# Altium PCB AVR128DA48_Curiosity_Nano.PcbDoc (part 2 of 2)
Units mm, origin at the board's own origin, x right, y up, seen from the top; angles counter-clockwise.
Board outline 83.82 x 20.32 mm, 4 copper layers (Top-Layer, Ground Plane, Power Plane, Bottom Layer), stack 1.59 mm thick; 66 components, 98 nets, 469 pads, 191 vias.
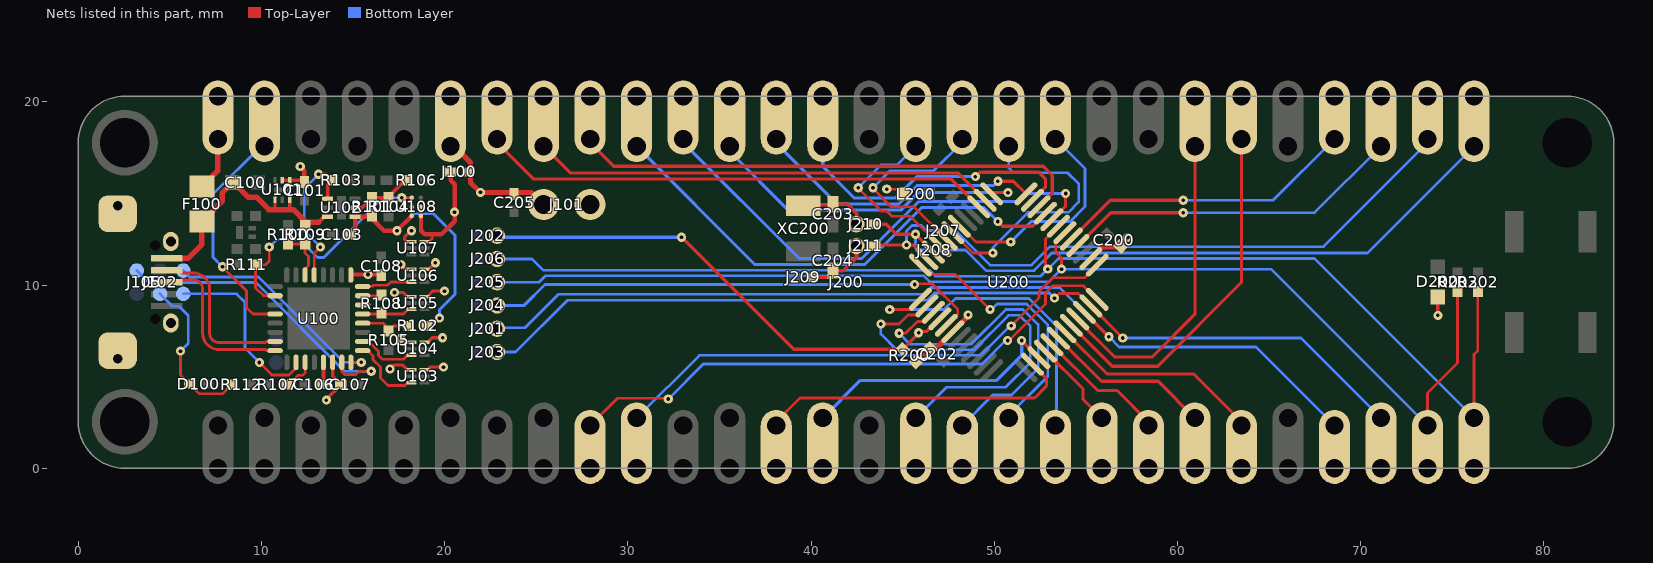
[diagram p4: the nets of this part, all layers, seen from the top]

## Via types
v1: diameter 0.5, hole 0.2, Top-Layer to Bottom Layer, 187 vias
v2: diameter 0.5, hole 0.2, Top-Layer to Bottom Layer, tented both sides, 2 vias
v3: diameter 0.5, hole 0.2, Top-Layer to Bottom Layer, tented top, 2 vias

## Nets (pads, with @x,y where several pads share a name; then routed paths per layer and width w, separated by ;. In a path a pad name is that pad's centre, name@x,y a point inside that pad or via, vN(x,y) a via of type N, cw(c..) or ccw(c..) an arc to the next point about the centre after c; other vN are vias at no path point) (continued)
PA6_SPI0_SCK: J200.13 U200.2 | length 17.1
  Top-Layer w0.175: J200.13@38.1,2.54 39.398,3.838 52.203,3.838 52.852,4.486 52.852,4.926 U200.2@52.09,5.688
PA7_SPI0_SS: J200.14 U200.3 | length 14.4
  Top-Layer w0.175: v1(51.5,6.975) 51.51,6.975 U200.3@52.444,6.041
  Bottom Layer w0.175: J200.14@40.64,2.743 42.697,4.8 50.13,4.8 51.5,6.17 v1(51.5,6.975)
PB0_UART3_TX: J200.20 U200.4 | length 4.9
  Top-Layer w0.175: U200.4@52.798,6.395 54.85,4.342 54.85,3.773 J200.20@55.88,2.743
PB1_UART3_RX: J200.21 U200.5 | length 7
  Top-Layer w0.175: U200.5@53.151,6.748 55.649,4.25 56.71,4.25 J200.21@58.42,2.54
PB2: J200.22 U200.6 | length 9.5
  Top-Layer w0.175: U200.6@53.505,7.102 55.856,4.75 58.953,4.75 J200.22@60.96,2.743 J200.22@60.96,2.54
PB3: J200.23 U200.7 | length 11.7
  Top-Layer w0.175: U200.7@53.858,7.455 56.164,5.15 60.89,5.15 J200.23@63.5,2.54
PB4: J200.34 U200.8 | length 19.7
  Top-Layer w0.175: U200.8@54.212,7.809 56.446,5.575 58.925,5.575 63.5,10.15 J200.34@63.5,17.78
PB5: J200.35 U200.9 | length 17.6
  Top-Layer w0.175: U200.9@54.565,8.162 54.565,8.083 56.573,6.075 58.625,6.075 60.96,8.41 J200.35@60.96,17.577 J200.35@60.96,17.78
PC0_UART1_TX: J200.25 J201.2 U200.10 | length 51.7
  Top-Layer w0.175: U200.10@54.919,8.516 56.261,7.174 v1@56.261,7.112
  Bottom Layer w0.15: J201.2@22.86,7.62 22.915,7.675 24.382,7.675 26.211,9.504 46.162,9.504 46.534,9.875 53.573,9.875 v1(56.261,7.187) 56.819,6.629 64.287,6.629 J200.25@68.58,2.337
PC1_UART1_RX: J200.26 J203.2 U200.11 | length 52.7
  Top-Layer w0.15: v1(53.291,9.292) 53.541,9.541 54.601,9.541 U200.11@55.272,8.87
  Top-Layer w0.175: U200.11@55.272,8.87 56.896,7.246 56.896,7.112 v1(57.023,7.112)
  Bottom Layer w0.15: J203.2@22.86,6.35 23.869,6.35 26.694,9.175 46.351,9.175 46.752,9.575 53.007,9.575 v1(53.291,9.292) ; v1(57.023,7.112) 66.751,7.112 J200.26@71.12,2.743
PC2_I2C0_SDA: J200.9 U200.12 | length 31.5
  Top-Layer w0.15: J200.9@27.94,2.337 29.422,3.819 32.175,3.819 v1(32.209,3.785) ; v1(50.736,6.975) 50.799,6.975 52.798,8.974 52.798,9.573 53.189,9.964 54.882,9.964 55.624,9.223 U200.12@55.626,9.223
  Bottom Layer w0.15: v1(32.209,3.785) 34.118,5.694 49.345,5.694 50.625,6.975 v1(50.736,6.975)
PC3_I2C0_SCL: J200.10 U200.13 | length 28.8
  Top-Layer w0.15: v1(50.927,7.775) 52.444,9.292 52.444,9.643 53.199,10.398 54.927,10.398 U200.13@55.626,11.097
  Bottom Layer w0.15: J200.10@30.48,2.743 33.906,6.17 49.259,6.17 50.864,7.775 v1(50.927,7.775)
PC4: J200.31 U200.16 | length 18.8
  Top-Layer w0.175: U200.16@54.565,12.158 56.363,13.955 v1(60.325,13.955)
  Bottom Layer w0.15: v1(60.325,13.955) 67.498,13.955 J200.31@71.12,17.577
PC5: J200.32 U200.17 | length 16.6
  Top-Layer w0.175: U200.17@54.212,12.511 56.333,14.632 v1(60.325,14.632)
  Bottom Layer w0.15: v1(60.325,14.632) 65.229,14.632 J200.32@68.58,17.983
PC6_LED0_GPIO1: J200.27 J205.2 R203.1 U200.18 | length 65.2
  Top-Layer w0.15: v1(53.671,10.873) 53.671,11.487 53.359,11.799 53.359,12.366 U200.18@53.858,12.865 ; J200.27@73.66,2.337 73.66,4.115 75.3,5.755 R203.1@75.3,9.656
  Bottom Layer w0.15: J205.2@22.86,10.16 25.16,10.16 25.516,10.516 46.134,10.516 46.461,10.189 52.987,10.189 v1(53.671,10.873) 65.123,10.873 J200.27@73.66,2.337
PC7_SW0_GPIO0: J200.28 J206.2 R202.1 U200.19 | length 72.3
  Top-Layer w0.15: v1(52.928,10.873) 52.802,10.999 52.802,12.516 U200.19@53.505,13.218 ; J200.28@76.2,0.325 J200.28@76.2,2.743 76.2,6.223 76.405,6.428 R202.1@76.405,9.656
  Bottom Layer w0.15: J206.2@22.86,11.43 24.763,11.43 25.377,10.816 46.467,10.816 46.794,10.489 52.543,10.489 v1(52.928,10.873) 53.515,11.461 67.483,11.461 J200.28@76.2,2.743 J200.28@76.2,0.325
PD0_AIN0_WO0: J200.46 U200.20 | length 26.7
  Top-Layer w0.175: U200.20@53.151,13.572 53.9,14.321 v1(53.9,15)
  Bottom Layer w0.175: J200.46@33.02,17.78 39.347,11.453 42.76,11.453 45.869,14.563 51.299,14.563 51.737,15 v1(53.9,15)
PD1_AIN1_WO1: J200.47 U200.21 | length 27.2
  Top-Layer w0.175: v1(50.202,13.476) 50.46,13.218 52.09,13.218 U200.21@52.798,13.925
  Bottom Layer w0.175: J200.47@30.48,17.78 J200.47@30.48,17.577 36.929,11.128 42.939,11.128 46.049,14.238 49.441,14.238 v1(50.202,13.476)
PD2_AIN2_WO2: J200.48 U200.22 | length 28
  Top-Layer w0.175: J200.48@27.94,17.78 29.232,16.488 52.673,16.488 53.175,15.987 53.175,15.01 U200.22@52.444,14.279
PD3_AIN3: J200.43 U200.23 | length 16.4
  Top-Layer w0.175: v1(48.975,15.925) 49.213,16.163 52.436,16.163 52.798,15.802 52.798,15.34 U200.23@52.09,14.632
  Bottom Layer w0.175: J200.43@40.64,17.78 J200.43@40.64,17.577 40.64,16.485 42.375,14.75 44.607,14.75 45.782,15.925 v1(48.975,15.925)
PD4_AIN4: J200.44 U200.24 | length 15.8
  Top-Layer w0.175: v1(50.2,15.675) 51.048,15.675 U200.24@51.737,14.986
  Bottom Layer w0.175: J200.44@38.1,17.748 41.423,14.425 44.775,14.425 45.787,15.438 49.963,15.438 v1(50.2,15.675)
PD5_AIN5: J200.45 U200.25 | length 18.1
  Top-Layer w0.175: U200.25@49.863,14.986 49.927,15.05 v1(50.75,15.05)
  Bottom Layer w0.175: J200.45@35.56,17.545 35.56,17.295 38.755,14.1 44.909,14.1 45.859,15.05 v1(50.75,15.05)
PD6_AIN6: J200.49 U200.26 | length 25.5
  Top-Layer w0.175: J200.49@25.4,17.78 J200.49@25.4,17.577 26.85,16.127 48.015,16.127 U200.26@49.51,14.632
PD7_AIN7: J200.50 U200.27 | length 27.7
  Top-Layer w0.175: J200.50@22.86,17.78 24.838,15.802 47.633,15.802 U200.27@49.156,14.279
PE0: J200.38 U200.30 | length 12.4
  Top-Layer w0.15: U200.30@48.095,13.218 48.136,13.218 49.004,12.351 50.896,12.351 v1(50.906,12.36)
  Bottom Layer w0.15: v1(50.906,12.36) 52.025,13.479 54.15,13.479 54.962,14.291 54.962,16.361 J200.38@53.34,17.983
PE1: J200.39 U200.31 | length 15
  Top-Layer w0.15: U200.31@47.742,12.865 48.845,11.761 v1(49.93,11.761)
  Bottom Layer w0.15: v1(49.93,11.761) 49.93,12.056 51.849,13.975 54.05,13.975 54.61,14.535 54.61,15.54 54.017,16.133 51.06,16.133 50.8,16.392 J200.39@50.8,17.577
PE2: J200.40 U200.32 | length 11.3
  Top-Layer w0.15: v1(43.386,15.315) 43.386,15.269 44.381,14.274 45.625,14.274 U200.32@47.388,12.511
  Bottom Layer w0.15: v1(43.386,15.315) 44.317,16.245 46.693,16.245 48.26,17.812 J200.40@48.26,17.983
PE3: J200.41 U200.33 | length 9.8
  Top-Layer w0.15: v1(42.576,15.315) 43.855,14.035 44.157,14.035 44.436,13.755 45.437,13.755 U200.33@47.035,12.158
  Bottom Layer w0.15: v1(42.576,15.315) 43.822,16.56 44.704,16.56 J200.41@45.72,17.577
PF0: J200.29 J208.2 | length 32.4
  Bottom Layer w0.15: J208.2@47.094,11.913 48.437,11.913 49.561,10.789 52.172,10.789 53.143,11.761 56.689,11.761 70.384,11.761 J200.29@76.2,17.577
PF0_TOSC1: J208.1 J210.1 U200.34 | length 5.2
  Top-Layer w0.175: J210.1@43.546,13.326 44.111,13.326 44.657,12.78 v1(45.705,12.78) U200.34@46.681,11.804
  Bottom Layer w0.15: v1(45.705,12.78) 45.705,12.073 45.86,11.918 J208.1@46.344,11.918
PF1: J200.30 J207.2 | length 29.6
  Bottom Layer w0.15: J207.2@47.594,12.979 47.889,12.979 49.779,11.089 52.047,11.089 53.058,12.1 56.792,12.1 67.98,12.1 J200.30@73.66,17.78
PF1_TOSC2: J207.1 J211.1 U200.35 | length 5.7
  Top-Layer w0.175: J211.1@43.597,12.192 v1(45.212,12.192) 45.586,12.192 U200.35@46.328,11.45
  Bottom Layer w0.15: v1(45.212,12.192) 45.212,12.959 45.508,13.255 46.022,13.255 46.298,12.979 J207.1@46.844,12.979
PF2: J200.18 U200.36 | length 14.5
  Top-Layer w0.15: U200.36@45.974,11.097 46.473,10.598 47.854,10.598 v1(49.777,8.675)
  Bottom Layer w0.15: v1(49.777,8.675) 49.849,8.675 50.149,8.975 51.775,8.975 52.928,7.822 52.928,5.028 50.8,2.9 J200.18@50.8,2.743
PF3: J200.19 U200.37 | length 17.3
  Top-Layer w0.15: v1(44.299,8.665) 45.416,8.665 U200.37@45.974,9.223
  Bottom Layer w0.15: v1(44.299,8.665) 47.271,8.665 47.882,9.275 51.899,9.275 53.4,7.774 53.4,2.397 J200.19@53.34,2.337
PF4_UART2_TX: J200.16 U200.38 | length 22.5
  Top-Layer w0.15: v1(43.812,7.88) 44.804,7.88 45.289,8.365 45.823,8.365 U200.38@46.328,8.87
  Bottom Layer w0.15: v1(43.812,7.88) 43.812,7.324 44.661,6.475 48.902,6.475 50.777,8.35 51.387,8.35 51.975,7.762 51.975,5.775 50.624,4.424 47.401,4.424 J200.16@45.72,2.743
PF5_UART2_RX: J200.17 U200.39 | length 19.1
  Top-Layer w0.15: v1(44.812,7.377) 45.173,7.377 45.813,8.017 46.182,8.017 U200.39@46.681,8.516
  Bottom Layer w0.15: v1(44.812,7.377) 45.414,6.775 48.737,6.775 50.637,8.675 51.575,8.675 52.4,7.85 52.4,5.453 50.947,4 49.923,4 J200.17@48.26,2.337
PF6_RESET: J202.2 R200.2 U200.40 | length 27.4
  Top-Layer w0.175: v1(32.933,12.618) 39.047,6.504 R200.2@45.006,6.504 45.006,6.506 45.877,7.377 v1(45.877,7.4) 45.939,7.463 46.301,7.463 47.001,8.162 U200.40@47.035,8.162
  Bottom Layer w0.175: J202.2@22.95,12.71 23.042,12.618 v1(32.933,12.618)
REG_ADJUST: R101.2 R104.2 R106.1 U102.5 | length 3.4
  Top-Layer w0.2: U102.5@15.115,14.225 15.49,14.225 R101.2@16.04,14.775 16.965,14.775 16.965,14.85 R106.1@17.84,15.725
REG_ENABLE: R103.1 U100.13 U102.1 | length 8.3
  Top-Layer w0.15: U100.13@12.876,10.556 12.876,11.736 v1(13.215,12.075)
  Top-Layer w0.2: v1(13.115,16.05) 13.508,16.05 13.833,15.725 R103.1@13.865,15.725 13.615,15.475 U102.1@13.615,14.725
  Bottom Layer w0.15: v1(13.115,16.05) 12.34,15.275 12.34,12.95 v1(13.215,12.075)
RESERVED: U100.6
S0_0_RX: R108.1 U100.5 U105.3 | length 2.8
  Top-Layer w0.15: U100.5@15.52,8.424 17.74,8.424 17.991,8.675 U105.3@18.189,8.675
S0_2_TX: R108.2 U100.7 | length 1
  Top-Layer w0.15: U100.7@15.52,9.424 R108.2@16.515,9.424
S0_3_CLK: U100.8 U106.3 | length 2.8
  Top-Layer w0.15: U100.8@15.52,9.937 16.055,9.937 16.119,10 16.89,10 17.065,10.175 U106.3@18.189,10.175
S1_0_TX: U100.1 U103.3 | length 4
  Top-Layer w0.15: U100.1@15.52,6.424 15.797,6.424 16.09,6.131 16.09,5.925 16.49,5.525 16.49,4.934 16.905,4.519 17.834,4.519 17.99,4.675 U103.3@18.189,4.675
S1_1_RX: U100.2 U104.3 | length 3.3
  Top-Layer w0.15: U100.2@15.52,6.924 15.841,6.924 16.39,6.375 16.39,6.156 16.596,5.95 17.74,5.95 17.965,6.175 U104.3@18.189,6.175
S\R\S\T\: J102.6 U100.26 | length 9.9
  Top-Layer w0.15: v3(9.885,5.777) 10.562,5.1 11.498,5.1 11.884,5.486 U100.26@11.884,5.787
  Bottom Layer w0.15: J102.6@5.73,9.525 8.64,9.525 9.1,9.065 9.1,6.562 v3(9.885,5.777)
SHIELD: J105.6 J105.7 J105.8 J105.9
STATUS_LED: R107.2 U100.27 | length 1.8
  Top-Layer w0.15: R107.2@11.39,4.575 11.493,4.575 11.993,5.075 12.24,5.075 12.393,5.228 U100.27@12.393,5.777
SWCLK: J102.1 U100.31 | length 17.3
  Top-Layer w0.15: U100.31@14.384,5.787 14.384,5.281 14.544,5.122 15.165,5.122 15.34,5.297 v1(15.99,5.297)
  Bottom Layer w0.15: J102.1@3.19,10.795 3.835,10.15 9.69,10.15 14.543,5.297 v1(15.99,5.297)
SWDIO: J102.5 U100.32 | length 12.4
  Top-Layer w0.15: U100.32@14.88,5.784 v1(15.449,5.784)
  Bottom Layer w0.15: J102.5@5.73,10.795 6.075,10.45 9.84,10.45 14.506,5.784 v1(15.449,5.784)
UPDI: J204.2 U200.41 | length 27.3
  Top-Layer w0.15: v1(45.658,10.035) 45.698,10.075 46.607,10.075 48.017,8.665 48.017,8.438 U200.41@47.388,7.809
  Bottom Layer w0.15: J204.2@22.95,8.885 24.327,8.885 ; 25.477,10.035 v1(45.658,10.035)
  Bottom Layer w0.175: 24.327,8.885 25.477,10.035
USBD_N: J105.2 U100.23 | length 9.2
  Top-Layer w0.16: J105.2@4.83,10.81 5.505,10.81 5.649,10.666 6.281,10.666 cw(c6.281,9.777) 7.17,9.777 7.17,7.375 ccw(c7.681,7.375) 7.681,6.864 10.214,6.864 10.274,6.924 U100.23@10.74,6.924
USBD_P: J105.3 U100.24 | length 9.2
  Top-Layer w0.16: J105.3@4.83,10.16 5.505,10.16 5.631,10.286 6.279,10.286 cw(c6.279,9.775) 6.79,9.775 6.79,7.373 ccw(c7.679,7.373) 7.679,6.484 10.214,6.484 10.274,6.424 U100.24@10.74,6.424
V\O\F\F\: J200.55 U100.20 | length 12.5
  Top-Layer w0.15: v1(7.87,11) 9.175,9.695 9.175,8.79 9.541,8.424 U100.20@10.74,8.424
  Bottom Layer w0.15: v1(7.87,11) 7.346,11.524 7.346,14.966 9.957,17.577 J200.55@10.16,17.577
VBUS: F100.1 J200.56 | length 2.8
  Top-Layer w0.3: F100.1@6.75,15.377 7.62,16.247 J200.56@7.62,17.78
VBUS_ADC: R100.1 R109.1 U100.14 | length 2.8
  Top-Layer w0.15: R100.1@11.439,12.25 12.376,12.25 12.376,11.764 12.565,11.575 12.565,11.068 12.376,10.879 U100.14@12.376,10.556
VCC_EDGE: C205.1 J100.2 J101.1 J200.51 | length 7.1
  Top-Layer w0.25: J200.51@20.32,17.78 J200.51@20.425,17.675
  Top-Layer w0.27: J200.51@20.425,17.675 21.407,16.693 21.407,15.593 21.935,15.065 v1(21.96,15.065) 24.737,15.065 J101.1@25.4,14.402
VCC_LEVEL: J100.1 U103.6 U104.6 U105.6 U106.6 U107.6 U108.A1 U108.B1 | length 11.2
  Top-Layer w0.15: U105.6@18.889,9.375 19.064,9.375 19.089,9.4 19.089,9.414 19.35,9.675 v1(19.99,9.675) ; U107.6@18.889,12.375 18.914,12.4 19.167,12.4 19.315,12.548 19.315,12.767
  Top-Layer w0.175: U103.6@18.889,5.375 19.065,5.375 19.215,5.525 v1(19.94,5.525) ; U104.6@18.889,6.875 19.065,6.875 19.315,7.125 v1(19.89,7.125) ; U106.6@18.889,10.875 19.14,10.875 v1(19.49,11.225)
  Top-Layer w0.2: U108.A1@18.702,13.775 U108.B1@18.702,14.275
  Top-Layer w0.225: 18.702,12.963 U108.A1@18.702,13.775
  Top-Layer w0.25: 18.714,12.963 18.909,12.767 19.315,12.767 19.822,12.767 20.54,13.485 v1(20.54,13.985) 20.54,15.5 20.32,15.72 J100.1@20.32,16.2
VCC_MCU_CORE: C106.2 U100.29 | length 1.2
  Top-Layer w0.2: C106.2@13.34,4.575 13.384,4.619 U100.29@13.384,5.787
VCC_P3V3: C101.2 C107.1 C108.1 D100.2 J102.4 R112.1 U100.9 U100.30 U101.1 U101.2 U103.1 U104.1 U105.1 U106.1 U107.1 | length 20.4
  Top-Layer w0.15: v1(5.575,6.4) 5.575,5.096 D100.2@6.071,4.6 6.596,4.075 7.89,4.075 R112.1@8.39,4.575 ; D100.2@5.99,4.575 D100.2@6.14,4.425
  Top-Layer w0.175: U101.2@11.139,15.725 12.239,15.725 C101.2@12.339,15.625 ; v1(17.015,5.425) 17.228,5.638 17.706,5.638 17.968,5.375 U103.1@18.189,5.375 ; v1(17.264,9.6) 17.74,9.6 17.965,9.375 U105.1@18.189,9.375 ; v1(17.599,11.125) 17.849,10.875 U106.1@18.189,10.875 ; v1(17.615,7.1) 17.84,6.875 U104.1@18.189,6.875 ; U107.1@18.189,12.375 18.177,12.388 17.913,12.388 17.81,12.49 17.81,12.635 18.148,12.973 v1(18.189,12.973)
  Top-Layer w0.2: v1(13.54,3.725) 13.54,3.775 C107.1@14.34,4.575 13.884,5.031 U100.30@13.884,5.787 ; U100.9@14.876,10.581 v1(15.815,10.581) 16.429,10.581 C108.1@16.515,10.495
  Top-Layer w0.25: v1(12.115,16.475) 12.339,16.251 C101.2@12.339,15.625
  Bottom Layer w0.15: J102.4@4.46,9.525 5.135,8.85 5.5,8.85 6,8.35 6,6.825 v1(5.575,6.4)
VCC_REGULATOR: C103.2 R101.1 R102.2 U102.4 U108.A2 U108.B2 | length 15.2
  Top-Layer w0.175: R102.2@19.039,7.875 19.113,7.95 19.465,7.95 v1(19.715,8.2) ; v1@19.765,8.175 v1@19.79,8.2
  Top-Layer w0.2: R101.1@16.04,13.62 R101.1@16.04,13.775 ; U108.A2@18.202,13.775 U108.B2@18.202,14.275
  Top-Layer w0.225: v1(17.4,12.973) U108.A2@18.202,13.775
  Top-Layer w0.24: C103.2@14.845,12.75 15.115,13.02 U102.4@15.115,13.725 15.99,13.725 R101.1@16.04,13.775
  Top-Layer w0.25: R101.1@16.04,13.62 16.687,12.973 v1(17.4,12.973)
  Bottom Layer w0.15: v1(17.4,12.973) 18.327,13.9 19.387,13.9 20.565,12.722 20.565,9.504 19.715,8.654 v1(19.715,8.2)
VCC_TARGET: C200.2 C202.1 D200.2 J101.2 L200.1 R200.1 U200.14 U200.42 | length 8.5
  Top-Layer w0.15: v1(44.131,15.24) 44.938,15.24 L200.1@45.113,15.065
  Top-Layer w0.175: U200.42@47.742,7.455 U200.42@47.742,7.483
  Top-Layer w0.2: v1@74.221,8.504 D200.2@74.221,9.356
  Top-Layer w0.25: v1@74.221,8.504 v1@74.298,8.427
  Top-Layer w0.27: R200.1@45.714,5.796 46.476,6.559 C202.1@46.527,6.559 ; C202.1@46.492,6.594 46.881,6.594 U200.42@47.742,7.455 ; U200.42@47.742,7.483 48.577,8.318 v1(48.577,8.375) ; U200.14@55.245,11.43 55.89,12.075 56.759,12.075 56.759,12.077 v1(57.282,12.6)
  other v1: 74.221,8.35
VCC_VBUS: C100.2 F100.2 J105.1 R109.2 U101.4 U101.6 U102.3 | length 13.8
  Top-Layer w0.175: 10.739,14.151 U101.4@10.739,14.675 ; 11.539,14.151 U101.6@11.539,14.675
  Top-Layer w0.24: 13.115,13.425 13.415,13.725 U102.3@13.615,13.725
  Top-Layer w0.3: J105.1@4.83,11.46 5.989,11.46 6.75,12.221 F100.2@6.75,13.477 7.87,14.597 7.87,15.048 C100.2@8.419,15.597 ; C100.2@8.444,15.622 9.267,14.8 9.724,14.8 10.399,14.125 11.74,14.125 12.389,13.476 R109.2@12.389,13.425 ; R109.2@12.389,13.25 R109.2@12.389,13.425 ; 13.115,13.425 R109.2@12.389,13.425
VTG_ADC: R102.1 R105.2 U100.4 | length 2.8
  Top-Layer w0.15: U100.4@15.52,7.924 16.64,7.924 R105.2@17.003,7.561 ; R105.2@16.94,7.499 R105.2@17.003,7.561 ; R102.1@18.039,7.775 17.216,7.775 R105.2@17.003,7.561
VTG_EN: R111.1 U100.18 U108.C2 | length 13.8
  Top-Layer w0.15: v1(10.425,12.075) 10.425,11.321 10.216,11.112 R111.1@9.675,11.112 9.675,9.85 10.101,9.424 U100.18@10.74,9.424 ; v1(17.659,14.775) U108.C2@18.202,14.775
  Bottom Layer w0.15: v1(10.425,12.075) 10.825,12.475 12.09,12.475 13.058,11.507 13.397,11.507 16.665,14.775 v1(17.659,14.775)
XIN: C203.2 J210.2 XC200.2 | length 3.7
  Top-Layer w0.2: XC200.2@39.572,14.381 C203.2@41.153,14.381 ; C203.2@41.196,14.424 41.976,14.424 42.5,13.9 J210.2@42.5,13.326
XOUT: C204.1 J209.1 J211.2 | length 3.1
  Top-Layer w0.18: J209.1@40.047,10.428 C204.1@40.937,10.428
  Top-Layer w0.2: C204.1@41.196,10.788 41.763,10.788 42.48,11.505 J211.2@42.48,12.088
pads on no net: J102.3 J105.0 J105.4 J105.10 J105.11 J200.0 J207.5 J208.5 Q101.0 U101.0 U101.5 U103.0 U104.0 U105.0 U106.0 U107.0

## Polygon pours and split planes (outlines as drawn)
GND on Bottom Layer "Bottom Layer-GND" (solid, remove dead copper, pour order 2): 83.82,20.32 83.82,0 0,0 0,20.32
GND on Top-Layer "Top Layer-GND" (solid, remove dead copper, pour order 4): 83.82,20.32 83.82,0 0,0 0,20.32
GND on Ground Plane (split plane): 81.479,19.802 81.676,19.773 81.87,19.724 82.058,19.657 82.238,19.572 82.409,19.469 82.569,19.351 82.717,19.217 82.851,19.069 82.969,18.909 83.072,18.738 83.157,18.558 83.224,18.37 83.273,18.176 83.302,17.979 83.311,17.796 83.31,17.78 83.31,2.54 83.311,2.524 83.302,2.341 83.273,2.144 83.224,1.95 83.157,1.762 83.072,1.582 82.969,1.411 82.851,1.251 82.717,1.103 82.569,0.969 82.409,0.851 82.238,0.748 82.058,0.663 81.87,0.596 81.676,0.547 81.479,0.518 81.296,0.509 81.28,0.51 2.54,0.51 2.524,0.509 2.341,0.518 2.144,0.547 1.95,0.596 1.762,0.663 1.582,0.748 1.411,0.851 1.251,0.969 1.103,1.103 0.969,1.251 0.851,1.411 0.748,1.582 0.663,1.762 0.596,1.95 0.547,2.144 0.518,2.341 0.509,2.524 0.51,2.54 0.51,17.78 0.509,17.796 0.518,17.979 0.547,18.176 0.596,18.37 0.663,18.558 0.748,18.738 0.851,18.909 0.969,19.069 1.103,19.217 1.251,19.351 1.411,19.469 1.582,19.572 1.762,19.657 1.95,19.724 2.144,19.773 2.341,19.802 2.524,19.811 2.54,19.81 81.28,19.81 81.296,19.811
VCC_P3V3 on Power Plane (split plane): 2.54,19.81 18.913,19.81 18.899,14.6 18.899,4.55 18.899,0.51 2.54,0.51 2.524,0.509 2.341,0.518 2.144,0.547 1.95,0.596 1.762,0.663 1.582,0.748 1.411,0.851 1.251,0.969 1.103,1.103 0.969,1.251 0.851,1.411 0.748,1.582 0.663,1.762 0.596,1.95 0.547,2.144 0.518,2.341 0.509,2.524 0.51,2.54 0.51,17.78 0.509,17.796 0.518,17.979 0.547,18.176 0.596,18.37 0.663,18.558 0.748,18.738 0.851,18.909 0.969,19.069 1.103,19.217 1.251,19.351 1.411,19.469 1.582,19.572 1.762,19.657 1.95,19.724 2.144,19.773 2.341,19.802 2.524,19.811
VCC_TARGET on Power Plane (split plane): 81.479,19.802 81.676,19.773 81.87,19.724 82.058,19.657 82.238,19.572 82.409,19.469 82.569,19.351 82.717,19.217 82.851,19.069 82.969,18.909 83.072,18.738 83.157,18.558 83.224,18.37 83.273,18.176 83.302,17.979 83.311,17.796 83.31,17.78 83.31,2.54 83.311,2.524 83.302,2.341 83.273,2.144 83.224,1.95 83.157,1.762 83.072,1.582 82.969,1.411 82.851,1.251 82.717,1.103 82.569,0.969 82.409,0.851 82.238,0.748 82.058,0.663 81.87,0.596 81.676,0.547 81.479,0.518 81.296,0.509 81.28,0.51 19.201,0.51 19.201,4.399 21.715,4.399 21.754,4.404 21.791,4.419 21.822,4.443 21.846,4.474 21.861,4.511 21.866,4.55 21.866,14.6 21.861,14.639 21.846,14.676 21.822,14.707 21.791,14.731 21.754,14.746 21.715,14.751 19.202,14.751 19.216,19.81 81.28,19.81 81.296,19.811
VCC_LEVEL on Power Plane (split plane): 21.564,4.701 19.201,4.701 19.201,14.449 21.564,14.449

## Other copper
Top-Layer:
  pour cut-out: 25.4,13.564 27.94,13.564 27.94,15.24 25.4,15.24
  pour cut-out: 42.03,11.557 44.1,11.557 44.1,13.943 42.03,13.943
Bottom Layer:
  pour cut-out: 23.45,13.356 23.45,5.694 21.335,5.694 21.335,13.356
Power Plane (plane layer: these items are gaps in the copper):
  lines w0.3: 19.05,0 19.05,4.55 ; 19.066,20.32 19.05,14.6 ; 19.05,4.55 19.05,14.6 ; 19.05,4.55 21.715,4.55 21.715,14.6 19.05,14.6

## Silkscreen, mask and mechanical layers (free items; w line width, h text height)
Top Overlay:
  circle w0.4: c6.346,1.365 r0.2
  lines w0.1: 10.428,15 10.428,15.4 ; 11.85,15 11.85,15.4
  lines w0.15: 4.064,4.039 19.504,4.039 19.64,4.175 19.64,16.15 19.534,16.256 4.064,16.256
  text "GND" at 5.497,16.58 h0.9 r90
  text "PD7" at 21.985,16 h0.75
  text "PD2" at 26.94,16 h0.75
  text "PD0" at 32.02,16 h0.75
  text "PD4" at 37.225,16 h0.75
  text "GND" at 42.18,16 h0.75
  text "PE2" at 47.26,16 h0.75
  text "PE0" at 52.34,16 h0.75
  text "PA2" at 57.36,16 h0.75
  text "PB4" at 62.5,16 h0.75
  text "PC5" at 67.58,16 h0.75
  text "PD6" at 24.4,15.575 h0.75
  text "PD1" at 29.48,15.575 h0.75
  text "PD5" at 34.56,15.575 h0.75
  text "PD3" at 39.64,15.575 h0.75
  text "PE3" at 44.72,15.575 h0.75
  text "PE1" at 49.9,15.575 h0.75
  text "PA3" at 54.927,15.575 h0.75
  text "PB5" at 59.96,15.575 h0.75
  text "GND" at 65.04,15.575 h0.75
  text "PC4" at 70.12,15.575 h0.75
  text "SW0" at 79.391,14.097 h0.75
  text "(PF1)" at 74.05,13.7 h0.75 r90
  text "(PF0)" at 76.625,13.3 h0.75 r90
  text "POWER" at 24.921,12.5 h0.75
  text "LED0" at 72.989,12.323 h0.75
  text "32KHz" at 37.925,11.075 h0.9 r90
  text "C" at 58.59,8.485 h6
  text "PC6" at 73.325,7.79 h0.75
  text "DEBUGGER" at 7.125,6.776 h0.75 r90
  text "AVR128DA48" at 54.635,5.475 h0.9
  text "PS" at 5.946,5.175 h0.75
  text "PC7" at 79.25,4.8 h0.75
  text "AVR128DA48 / CURIOSITY NANO" at 21.995,4.785 h1.35 r90
  text "PA1" at 24.525,3.95 h0.75
  text "PC3" at 29.48,3.95 h0.75
  text "PA5" at 34.56,3.95 h0.75
  text "PA7" at 39.64,3.95 h0.75
  text "PF4" at 44.72,3.95 h0.75
  text "PF2" at 49.8,3.95 h0.75
  text "PB0" at 54.88,3.95 h0.75
  text "PB2" at 59.96,3.95 h0.75
  text "GND" at 65.04,3.95 h0.75
  text "PC1" at 70.245,3.95 h0.75
  text "PC7" at 75.2,3.95 h0.75
  text "PA0" at 21.86,3.575 h0.75
  text "PC2" at 26.94,3.575 h0.75
  text "PA4" at 32.02,3.575 h0.75
  text "PA6" at 37.1,3.575 h0.75
  text "GND" at 42.18,3.575 h0.75
  text "PF5" at 47.385,3.575 h0.75
  text "PF3" at 52.34,3.575 h0.75
  text "PB1" at 57.545,3.575 h0.75
  text "PB3" at 62.5,3.575 h0.75
  text "PC0" at 67.58,3.575 h0.75
  text "PC6" at 72.66,3.575 h0.75
  text "GND" at 5.497,1.34 h0.9 r90
  text "b" at 28.575,1.075 h12
Bottom Overlay:
  lines w0.1: 45.825,11.15 48.12,11.15 48.12,13.741 45.825,13.741 45.825,11.15
  lines w0.12: 18,13.42 24.79,13.42 ; 25.959,13.42 26.625,13.42 ; 48.15,12.425 48.875,12.425 49.525,13.075 71.8,13.075 75.775,13.075 75.85,13.15 ; 72.638,13.087 73.2,13.65
  lines w0.15: 18,13.42 18,5.625 26.625,5.625 26.625,13.42 ; 21.25,5.625 21.25,13.42 ; 23.625,5.625 23.625,13.42
  text "GND" at 5.497,18.98 h0.9 r90
  text "(PF1)" at 74,16.75 h0.75 r90
  text "VBUS" at 7.995,16.443 h0.75 r90
  text "(PF0)" at 76.65,16.375 h0.75 r90
  text "D3" at 13.325,15.95 h0.75
  text "GND" at 18.78,15.95 h0.75
  text "PD7" at 23.86,15.95 h0.75
  text "PD2" at 28.94,15.95 h0.75
  text "PD0" at 34.02,15.95 h0.75
  text "PD4" at 38.975,15.95 h0.75
  text "GND" at 44.18,15.95 h0.75
  text "PE2" at 49.26,15.95 h0.75
  text "PE0" at 54.34,15.95 h0.75
  text "PA2" at 59.295,15.95 h0.75
  text "PB4" at 64.5,15.95 h0.75
  text "PC5" at 69.58,15.95 h0.75
  text "VOFF" at 11.385,15.625 h0.75
  text "D0" at 15.715,15.625 h0.75
  text "VTG" at 21.17,15.625 h0.75
  text "PD6" at 26.25,15.625 h0.75
  text "PD1" at 31.33,15.625 h0.75
  text "PD5" at 36.41,15.625 h0.75
  text "PD3" at 41.49,15.625 h0.75
  text "PE3" at 46.57,15.625 h0.75
  text "PE1" at 51.65,15.625 h0.75
  text "PA3" at 56.73,15.625 h0.75
  text "PB5" at 61.834,15.625 h0.75
  text "GND" at 66.89,15.625 h0.75
  text "PC4" at 71.97,15.625 h0.75
  text "CONNECTIONS" at 24.199,14.025 h0.7
  text "PF1" at 45.462,12.65 h0.75
  text "DEBUGGER" at 17.665,12.397 h0.75 r90
  text "D3" at 20.945,12.325 h0.75
  text "PF6" at 26.358,12.335 h0.75
  text "TARGET" at 27.725,11.647 h0.75 r90
  text "PF0" at 45.462,11.48 h0.75
  text "D2" at 20.945,11.055 h0.75
  text "PC7" at 26.358,11.06 h0.75
  text "c" at 16.61,10.475 h6.8
  text "D1" at 20.945,9.785 h0.75
  text "PC6" at 26.358,9.785 h0.75
  text "A08-3002 Rev3" at 63.05,8.925 h2
  text "D0" at 20.945,8.515 h0.75
  text "UPDI" at 26.358,8.51 h0.75
  text "CDC" at 19.179,7.985 h0.75 r90
  text "RX" at 20.945,7.245 h0.75
  text "PC0" at 26.358,7.235 h0.75
  text "t" at 14.776,7.05 h4.57
  text "GND" at 10.115,6.672 h0.75
  text "R" at 36.474,6.528 h4
  text "Microchip © 2019" at 63.375,6.4 h2
  text "TX" at 20.945,5.975 h0.75
  text "PC1" at 26.358,5.96 h0.75
  text "BOOT" at 10.115,5.402 h0.75
  text "CDC" at 14.955,4.825 h0.75
  text "ID" at 10.722,3.925 h0.75
  text "TX" at 15.865,3.925 h0.75
  text "D2" at 20.945,3.925 h0.75
  text "PA1" at 26.275,3.925 h0.75
  text "PC3" at 31.48,3.925 h0.75
  text "PA5" at 36.56,3.925 h0.75
  text "PA7" at 41.64,3.925 h0.75
  text "PF4" at 46.72,3.925 h0.75
  text "PF2" at 51.8,3.925 h0.75
  text "PB0" at 56.88,3.925 h0.75
  text "PB2" at 61.96,3.925 h0.75
  text "GND" at 67.04,3.925 h0.75
  text "PC1" at 71.995,3.925 h0.75
  text "PC7" at 77.2,3.925 h0.75
  text "GND" at 5.497,3.74 h0.9 r90
  text "NC" at 8.245,3.55 h0.75
  text "RX" at 13.325,3.55 h0.75
  text "D1" at 18.28,3.55 h0.75
  text "PA0" at 23.86,3.55 h0.75
  text "PC2" at 28.94,3.55 h0.75
  text "PA4" at 34.02,3.55 h0.75
  text "PA6" at 39.1,3.55 h0.75
  text "GND" at 44.18,3.55 h0.75
  text "PF5" at 49.135,3.55 h0.75
  text "PF3" at 54.34,3.55 h0.75
  text "PB1" at 59.295,3.55 h0.75
  text "PB3" at 64.5,3.55 h0.75
  text "PC0" at 69.58,3.55 h0.75
  text "PC6" at 74.66,3.55 h0.75
Board (M1):
  the board outline again, w0.1
Conn. Pos. (M4):
  circle w0.35: c7.62,17.983 r0.65
  circle w0.35: c7.62,2.337 r0.65
  circle w0.35: c10.16,2.743 r0.65
  circle w0.35: c10.16,17.577 r0.65
  circle w0.35: c12.7,2.337 r0.65
  circle w0.35: c12.7,17.983 r0.65
  circle w0.35: c15.24,2.743 r0.65
  circle w0.35: c15.24,17.577 r0.65
  circle w0.35: c17.78,2.337 r0.65
  circle w0.35: c17.78,17.983 r0.65
  circle w0.35: c20.32,2.743 r0.65
  circle w0.35: c20.32,17.577 r0.65
  circle w0.35: c35.56,17.577 r0.65
  circle w0.35: c35.56,2.743 r0.65
  circle w0.35: c33.02,17.983 r0.65
  circle w0.35: c33.02,2.337 r0.65
  circle w0.35: c30.48,17.577 r0.65
  circle w0.35: c30.48,2.743 r0.65
  circle w0.35: c27.94,17.983 r0.65
  circle w0.35: c27.94,2.337 r0.65
  circle w0.35: c25.4,17.577 r0.65
  circle w0.35: c25.4,2.743 r0.65
  circle w0.35: c22.86,2.337 r0.65
  circle w0.35: c22.86,17.983 r0.65
  circle w0.35: c38.1,2.337 r0.65
  circle w0.35: c38.1,17.983 r0.65
  circle w0.35: c40.64,17.577 r0.65
  circle w0.35: c40.64,2.743 r0.65
  circle w0.35: c76.2,2.743 r0.65
  circle w0.35: c76.2,17.577 r0.65
  circle w0.35: c71.12,17.577 r0.65
  circle w0.35: c71.12,2.743 r0.65
  circle w0.35: c55.88,17.577 r0.65
  circle w0.35: c55.88,2.743 r0.65
  circle w0.35: c58.42,2.337 r0.65
  circle w0.35: c58.42,17.983 r0.65
  circle w0.35: c60.96,2.743 r0.65
  circle w0.35: c60.96,17.577 r0.65
  circle w0.35: c63.5,2.337 r0.65
  circle w0.35: c63.5,17.983 r0.65
  circle w0.35: c66.04,2.743 r0.65
  circle w0.35: c66.04,17.577 r0.65
  circle w0.35: c68.58,2.337 r0.65
  circle w0.35: c68.58,17.983 r0.65
  circle w0.35: c53.34,17.983 r0.65
  circle w0.35: c53.34,2.337 r0.65
  circle w0.35: c50.8,17.577 r0.65
  circle w0.35: c50.8,2.743 r0.65
  circle w0.35: c48.26,17.983 r0.65
  circle w0.35: c48.26,2.337 r0.65
  circle w0.35: c45.72,17.577 r0.65
  circle w0.35: c45.72,2.743 r0.65
  circle w0.35: c43.18,17.983 r0.65
  circle w0.35: c43.18,2.337 r0.65
  circle w0.35: c73.66,17.983 r0.65
  circle w0.35: c73.66,2.337 r0.65
  circle w0.4: c2.54,2.54 r1.6
  circle w0.4: c81.28,2.54 r1.6
  circle w0.4: c81.28,17.78 r1.6
  circle w0.4: c2.54,17.78 r1.6
  region: 1.04,14.884 1.04,12.784 2.94,12.784 2.94,14.884
  region: 2.94,5.484 2.94,7.584 1.04,7.584 1.04,5.484
  region: 5.68,11.285 5.68,11.635 3.98,11.635 3.98,11.285
  region: 5.68,10.635 5.68,10.985 3.98,10.985 3.98,10.635
  region: 5.68,9.985 5.68,10.335 3.98,10.335 3.98,9.985
  region: 5.68,9.335 5.68,9.685 3.98,9.685 3.98,9.335
  region: 5.68,8.685 5.68,9.035 3.98,9.035 3.98,8.685
  lines w0.35: 6.97,0 cw(c7.62,0) 8.27,0 ; 6.97,20.32 ccw(c7.62,20.32) 8.27,20.32 ; 9.51,0 cw(c10.16,0) 10.81,0 ; 9.51,20.32 ccw(c10.16,20.32) 10.81,20.32 ; 12.05,0 cw(c12.7,0) 13.35,0 ; 12.05,20.32 ccw(c12.7,20.32) 13.35,20.32 ; 14.59,0 cw(c15.24,0) 15.89,0 ; 14.59,20.32 ccw(c15.24,20.32) 15.89,20.32 ; 17.13,0 cw(c17.78,0) 18.43,0 ; 17.13,20.32 ccw(c17.78,20.32) 18.43,20.32 ; 19.67,0 cw(c20.32,0) 20.97,0 ; 19.67,20.32 ccw(c20.32,20.32) 20.97,20.32 ; 22.21,0 cw(c22.86,0) 23.51,0 ; 22.21,20.32 ccw(c22.86,20.32) 23.51,20.32 ; 24.75,0 cw(c25.4,0) 26.05,0 ; 24.75,20.32 ccw(c25.4,20.32) 26.05,20.32 ; 27.29,0 cw(c27.94,0) 28.59,0 ; 27.29,20.32 ccw(c27.94,20.32) 28.59,20.32 ; 29.83,0 cw(c30.48,0) 31.13,0 ; 29.83,20.32 ccw(c30.48,20.32) 31.13,20.32 ; 32.37,0 cw(c33.02,0) 33.67,0 ; 32.37,20.32 ccw(c33.02,20.32) 33.67,20.32 ; 34.91,0 cw(c35.56,0) 36.21,0 ; 34.91,20.32 ccw(c35.56,20.32) 36.21,20.32 ; 37.45,0 cw(c38.1,0) 38.75,0 ; 37.45,20.32 ccw(c38.1,20.32) 38.75,20.32 ; 39.99,0 cw(c40.64,0) 41.29,0 ; 39.99,20.32 ccw(c40.64,20.32) 41.29,20.32 ; 42.53,0 cw(c43.18,0) 43.83,0 ; 42.53,20.32 ccw(c43.18,20.32) 43.83,20.32 ; 45.07,0 cw(c45.72,0) 46.37,0 ; 45.07,20.32 ccw(c45.72,20.32) 46.37,20.32 ; 47.61,0 cw(c48.26,0) 48.91,0 ; 47.61,20.32 ccw(c48.26,20.32) 48.91,20.32 ; 50.15,0 cw(c50.8,0) 51.45,0 ; 50.15,20.32 ccw(c50.8,20.32) 51.45,20.32 ; 52.69,0 cw(c53.34,0) 53.99,0 ; 52.69,20.32 ccw(c53.34,20.32) 53.99,20.32 ; 55.23,0 cw(c55.88,0) 56.53,0 ; 55.23,20.32 ccw(c55.88,20.32) 56.53,20.32 ; 57.77,0 cw(c58.42,0) 59.07,0 ; 57.77,20.32 ccw(c58.42,20.32) 59.07,20.32 ; 60.31,0 cw(c60.96,0) 61.61,0 ; 60.31,20.32 ccw(c60.96,20.32) 61.61,20.32 ; 62.85,0 cw(c63.5,0) 64.15,0 ; 62.85,20.32 ccw(c63.5,20.32) 64.15,20.32 ; 65.39,0 cw(c66.04,0) 66.69,0 ; 65.39,20.32 ccw(c66.04,20.32) 66.69,20.32 ; 67.93,0 cw(c68.58,0) 69.23,0 ; 67.93,20.32 ccw(c68.58,20.32) 69.23,20.32 ; 70.47,0 cw(c71.12,0) 71.77,0 ; 70.47,20.32 ccw(c71.12,20.32) 71.77,20.32 ; 73.01,0 cw(c73.66,0) 74.31,0 ; 73.01,20.32 ccw(c73.66,20.32) 74.31,20.32 ; 75.55,0 cw(c76.2,0) 76.85,0 ; 75.55,20.32 ccw(c76.2,20.32) 76.85,20.32
  text "Connector Placement" at -0.051,24.409 h5
TP Pos. (M5):
  circle w0.5: c3.19,10.795 r0.25
  circle w0.5: c3.19,9.525 r0.25
  circle w0.5: c4.46,9.525 r0.25
  circle w0.5: c4.46,10.795 r0.25
  circle w0.5: c5.73,10.795 r0.25
  circle w0.5: c5.73,9.525 r0.25
  circle w0.4: c2.54,2.54 r1.6
  circle w0.4: c2.54,17.78 r1.6
  lines w0.1: 2.79,8.12 3.19,8.52 ; 2.79,12.2 3.19,11.8 ; 3.59,8.12 3.19,8.52 ; 3.59,12.2 3.19,11.8 ; 4.06,8.12 4.46,8.52 ; 4.86,8.12 4.46,8.52 ; 5.33,8.12 5.73,8.52 ; 5.33,12.2 5.73,11.8 ; 6.13,8.12 5.73,8.52 ; 6.13,12.2 5.73,11.8 ; 12.18,4.07 3.19,4.07 3.19,8.52 ; 12.18,5.82 4.46,5.82 4.46,8.52 ; 12.18,7.57 5.73,7.57 5.73,8.52 ; 12.18,12.75 5.73,12.75 5.73,11.8 ; 12.18,14.5 3.19,14.5 3.19,11.8
  text "Test Point Placement" at -0.051,21.717 h5
  text "J101-1_SWCLK" at 12.88,14.083 h1
  text "J101-5_SWD" at 12.88,12.333 h1
  text "J101-6_RST" at 12.88,6.903 h1
  text "J101-4_VCC" at 12.88,5.153 h1
  text "J101-2_GND" at 12.88,3.403 h1
  text "2x5 50mil test-point pattern" at 7.15,-2.025 h1
Test Jig (M9):
  circle w0.5: c-43.81,-5.475 r1.25
  circle w0.5: c-43.81,25.775 r1.25
  circle w0.5: c2.54,2.54 r1.5
  circle w0.5: c2.54,17.78 r1.5
  lines w0.5: -38.31,-12.225 -38.31,32.525 cw(c-36.81,32.525) -35.31,32.525 -6.31,32.525 cw(c-4.81,32.525) -3.31,32.525 -3.31,-12.225 ; -38.309,-12.225 ccw(c-36.809,-12.225) -35.309,-12.225 -6.309,-12.225 ccw(c-4.809,-12.225) -3.309,-12.225 ; -49.31,-20.225 -46.31,-23.225 86.47,-23.225 89.47,-20.226 89.47,40.5 86.47,43.5 -46.31,43.5 -49.31,40.5 -49.31,-20.225 ; 0.69,7.85 ccw(c2.19,7.85) 2.19,6.35 5.04,6.35 cw(c5.04,4.85) 6.54,4.85 6.54,4.04 ccw(c8.04,4.04) 8.04,2.54 59.19,2.54 ccw(c59.19,4.04) 60.69,4.04 60.69,16.28 ccw(c59.19,16.28) 59.19,17.78 8.04,17.78 ccw(c8.04,16.28) 6.54,16.28 6.54,15.47 cw(c5.04,15.47) 5.04,13.97 2.19,13.97 ccw(c2.19,12.47) 0.69,12.47 0.69,7.85
  text "Test Fixture Outline" at -21.638,36.109 h10
Test Jig Pin (M10):
  circle w0.1: c76.2,2.54 r2.85
  circle w0.1: c76.2,17.78 r2.85
  circle w0.5: c2.54,17.78 r2
  circle w0.5: c2.54,17.78 r1.25
  circle w0.5: c2.54,2.54 r1.25
  circle w0.5: c2.54,2.54 r2
  circle w0.1: c2.54,17.78 r2.85
  circle w0.1: c2.54,2.54 r2.85

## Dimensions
5.98,9.525 to 5.98,10.795 on TP Pos. (M5)
82.88,2.54 to 82.88,17.78 on Conn. Pos. (M4)
7.62,19.67 to 2.54,19.38 on Conn. Pos. (M4)
35.555,0 to 33.015,0 on Conn. Pos. (M4)
2.54,0 to 1.9,10.16 on Conn. Pos. (M4)
81.28,20.32 to 81.28,0 on Dimentions (M6)
83.82,2.54 to 0,2.54 on Dimentions (M6)
2.54,0.94 to 81.28,0.94 on Conn. Pos. (M4)
2.54,20.32 to 0.94,17.78 on Conn. Pos. (M4)
0,17.78 to 2.54,19.38 on Conn. Pos. (M4)
3.19,9.275 to 2.54,0.94 on TP Pos. (M5)
2.94,9.525 to 0.94,2.54 on TP Pos. (M5)
2.94,10.795 to 0.94,2.54 on TP Pos. (M5)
